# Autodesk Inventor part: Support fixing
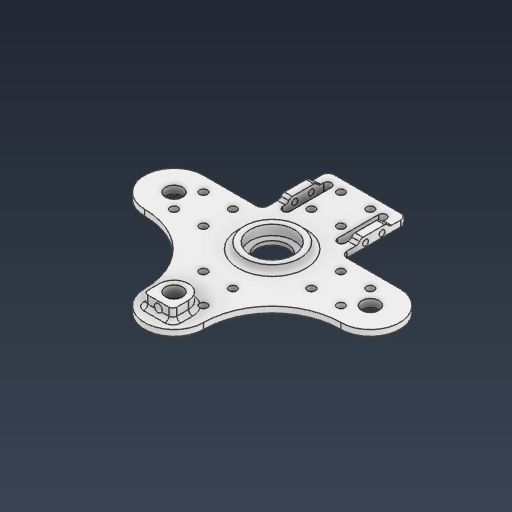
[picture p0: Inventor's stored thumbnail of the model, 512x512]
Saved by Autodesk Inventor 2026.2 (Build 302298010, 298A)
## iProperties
Created: 2026-04
Part Number: Support fixing
Material: ABS 플라스틱
Document SubType Name: Modeling
Designer: work
Density: 1.06 g/cm^3
Appearance: 매끄러움 - 흰색
Mass: 27.6357 g
Surface Area: 166.702 cm^2
Volume: 26.0714 cm^3
Author: work
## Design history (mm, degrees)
sketch "스케치1"
  geometry: L1 (0, 0)-(50, 0); L2 (0, 0)-(0, 50); L3 (0, 0)-(-50, 0); L4 (0, 0)-(0, -50); L5 (-15, 50)-(15, 50); L6 (-50, -15)-(-50, 15); L7 (15, -50)-(-15, -50); L8 (50, 15)-(50, -15); L9 (50, -15)-(-50, -15); L10 (20, -15)-(-20, -15); L11 (-20, -15)-(-20, -48.5); L12 (-20, -48.5)-(20, -48.5); L13 (20, -48.5)-(20, -15); L14 (-7.5, 42.5)-(7.5, 42.5); L15 (7.5, 42.5)-(7.5, 27.5); L16 (7.5, 27.5)-(-7.5, 27.5); L17 (-7.5, 27.5)-(-7.5, 42.5); L18 (-7.5, 42.5)-(7.5, 27.5); L19 (7.5, 42.5)-(-7.5, 27.5); L20 (-27.5, 7.5)-(-27.5, -7.5); L21 (-27.5, -7.5)-(-42.5, -7.5); L22 (-42.5, -7.5)-(-42.5, 7.5); L23 (-42.5, -7.5)-(-27.5, 7.5); L24 (-42.5, 7.5)-(-27.5, -7.5); L25 (-42.5, 7.5)-(-27.5, 7.5); L26 (-7.5, -27.5)-(7.5, -27.5); L27 (7.5, -27.5)-(7.5, -42.5); L28 (7.5, -42.5)-(-7.5, -42.5); L29 (7.5, -42.5)-(-7.5, -27.5); L30 (-7.5, -42.5)-(7.5, -27.5); L31 (-7.5, -42.5)-(-7.5, -27.5); L32 (27.5, -7.5)-(27.5, 7.5); L33 (27.5, 7.5)-(42.5, 7.5); L34 (42.5, 7.5)-(42.5, -7.5); L35 (42.5, 7.5)-(27.5, -7.5); L36 (42.5, -7.5)-(27.5, 7.5); L37 (42.5, -7.5)-(27.5, -7.5); C1 r 8 at (0, 0); C2 r 11.2 at (0, 0); C3 r 4.4 at (50, 0); C4 r 4.4 at (0, 50); C5 r 4.4 at (-50, 0); C6 r 4.4 at (0, -50); C7 r 2 at (7.5, 42.5); C8 r 2 at (-7.5, 42.5); C9 r 2 at (-7.5, 27.5); C10 r 2 at (7.5, 27.5); C11 r 2 at (-27.5, -7.5); C12 r 2 at (-42.5, -7.5); C13 r 2 at (-27.5, 7.5); C14 r 2 at (-42.5, 7.5); C15 r 2 at (7.5, -27.5); C16 r 2 at (7.5, -42.5); C17 r 2 at (-7.5, -27.5); C18 r 2 at (-7.5, -42.5); C19 r 2 at (27.5, 7.5); C20 r 2 at (42.5, 7.5); C21 r 2 at (27.5, -7.5); C22 r 2 at (42.5, -7.5); A1 r 15 centre (0, 50) between (15, 50) and (-15, 50); A2 r 15 centre (-50, 0) between (-50, 15) and (-50, -15); A3 r 15 centre (0, -50) between (-15, -50) and (15, -50); A4 r 15 centre (50, 0) between (50, -15) and (50, 15); A5 r 35 centre (50, 50) between (15, 50) and (50, 15); A6 r 35 centre (-50, 50) between (-50, 15) and (-15, 50); 10 further points
  constraints: 74 end point, 28 centre point, 25 coincident, 12 point on circle, 5 horizontal, 5 midpoint, 4 parallel, 3 tangent, 2 perpendicular, 2 point on line, 1 concentric, 117 other
  dimensions: "d0" = 16 diameter of C1; "d1" = 22.4 diameter of C2; "d2" = 50 distance of L1.start L1.end; "d3" = 8.8 diameter of C3; "d6" = 360 deg dimension on L1.start L1.end (derived); "d8" = 30 distance of L5.start L5.end; "d11" = 360 deg dimension on L1.start A1.centre (derived); "d14" = 40 distance of L11.end L12.end; "d21" = 15 distance of L15.end L16.end; "d22" = 15 distance of L14.end L15.end; "d23" = 35 distance of C1.centre point (0, 35); "d24" = 4 diameter of C7; "d25" = 4 diameter of C8; "d26" = 4 diameter of C9; "d27" = 4 diameter of C10; "d30" = 360 deg dimension on L1.start L16.end (derived); "d32" = 6 distance between parallel lines of L12 L28
  node "스케치 - 원형 패턴1" dims "d6" = 360 deg (derived)
  node "스케치 - 원형 패턴2" dims "d11" = 360 deg (derived)
  node "스케치 - 원형 패턴4" dims "d30" = 360 deg (derived)
extrude "돌출1" new body sketch "스케치1" distance "d33" = 4; taper "d34" = 0 deg
extrude "돌출2" join sketch "스케치1" distance "d35" = 2; taper "d36" = 0 deg
sketch "스케치2"
  geometry: C1 r 14.2 at (0, 0); C2 r 11.2 at (0, 0) reference; 1 further point
  constraints: 1 centre point, 1 coincident, 1 concentric
  dimensions: "d37" = 3 radial gap between concentric circles of C1 C2
extrude "돌출3" join sketch "스케치2" distance "d38" = 3; taper "d39" = 0 deg
fillet "모깎기1" dims "d40" = 3
sketch "스케치3"
  geometry: L1 (20, 38.75)-(16, 38.75); L2 (16, 38.75)-(16, 24.75); L3 (16, 24.75)-(20, 24.75); L4 (20, 24.75)-(20, 38.75); L5 (20, 18)-(20, 45.5) reference; L6 (17, 48.5)-(-17, 48.5) reference; L7 (0, 48.5)-(0, 0); L8 (-20, 38.75)-(-16, 38.75); L9 (-16, 38.75)-(-16, 24.75); L10 (-16, 24.75)-(-20, 24.75); L11 (-20, 24.75)-(-20, 38.75); 1 further point
  constraints: 18 end point, 4 symmetric about line, 3 midpoint, 2 parallel, 1 horizontal, 1 perpendicular, 1 vertical
  dimensions: "d41" = 4 distance of L2.end L3.end; "d42" = 14 distance of L1.end L2.end
extrude "돌출4" join sketch "스케치3" distance "d43" = 2; taper "d44" = 0 deg
sketch "스케치4"
  geometry: L1 (20.75, 6)-(6.75, 6) reference; L2 (13.75, 6)-(13.75, 0); L3 (9.55, 3)-(17.95, 3); L4 (20.75, 4)-(6.75, 4) reference; L5 (9.55, 3)-(17.95, 3); L6 (0, 0)-(27.5, 0) reference; C1 r 1.5 at (9.55, 3); C2 r 1.5 at (17.95, 3); 2 further points
  constraints: 6 end point, 3 midpoint, 2 centre point, 2 coincident, 1 collinear, 1 horizontal, 1 parallel, 1 vertical
  dimensions: "d45" = 8.4 distance of L3.start L3.end; "d46" = 0 distance between parallel lines of L3 L5 (derived); "d47" = 3 diameter of C1; "d48" = 3 diameter of C2; "d49" = 3 distance between parallel lines of L6 L3
extrude "돌출5" cut sketch "스케치4" distance "d50" = 4; taper "d51" = 0 deg
sketch "스케치5"
  geometry: L1 (16, 19.25)-(12, 19.25); L2 (12, 19.25)-(12, 44.25); L3 (12, 44.25)-(16, 44.25); L4 (16, 44.25)-(16, 19.25); L5 (16, 38.75)-(16, 24.75) reference; 2 further points
  constraints: 8 end point, 2 midpoint, 2 parallel, 1 horizontal, 1 perpendicular
  dimensions: "d52" = 4 distance of L2.end L3.end; "d53" = 25 distance of L1.end L2.end
extrude "돌출6" cut sketch "스케치5" distance "d54" = 4; taper "d55" = 0 deg
fillet "모깎기2" dims "d56" = 2
node "작업 평면1"
fillet "모깎기3" dims "d57" = 2
chamfer "모따기1" distance "d58" = 1; stored, may be unused: second distance "d59" = 2, angle "d60" = 45 deg
sketch "스케치6"
  geometry: L1 (-16, 40.75)-(-20, 40.75) reference; L2 (-16, 40.75)-(-16, 42.25) reference; L3 (-12, 42.25)-(-12, 21.25) reference; L4 (-16, 21.25)-(-16, 22.75) reference; L5 (-20, 22.75)-(-16, 22.75) reference; L6 (-20, 22.75)-(-20, 18) reference; L7 (-23, 15)-(-50, 15) reference; L8 (50, 15)-(23, 15) reference; L9 (20, 18)-(20, 22.75) reference; L10 (16, 22.75)-(20, 22.75) reference; L11 (16, 22.75)-(16, 21.25) reference; L12 (12, 21.25)-(12, 42.25) reference; L13 (16, 42.25)-(16, 40.75) reference; L14 (20, 40.75)-(16, 40.75) reference; L15 (20, 40.75)-(20, 45.5) reference; L16 (17, 48.5)-(-17, 48.5) reference; L17 (-20, 45.5)-(-20, 40.75) reference; L18 (7.4, -50)-(-7.4, -50); L19 (-7.4, -50)-(-7.4, -58); L20 (-7.4, -58)-(7.4, -58); L21 (7.4, -58)-(7.4, -50); C1 r 4.4 at (-50, 0) reference; C2 r 4.4 at (0, -50) reference; C3 r 4.4 at (50, 0) reference; C4 r 2 at (-27.5, 7.5) reference; C5 r 2 at (-27.5, -7.5) reference; C6 r 2 at (27.5, -7.5) reference; C7 r 2 at (27.5, 7.5) reference; C8 r 2 at (7.5, -27.5) reference; C9 r 2 at (-7.5, -42.5) reference; C10 r 2 at (7.5, -42.5) reference; C11 r 2 at (-7.5, -27.5) reference; C12 r 2 at (42.5, 7.5) reference; C13 r 2 at (42.5, -7.5) reference; C14 r 2 at (-42.5, -7.5) reference; C15 r 2 at (-42.5, 7.5) reference; C16 r 2 at (7.5, 42.5) reference; C17 r 2 at (-7.5, 42.5) reference; C18 r 2 at (-7.5, 27.5) reference; C19 r 2 at (7.5, 27.5) reference; C20 r 17.2 at (0, 0) reference; A1 r 2 centre (-14, 42.25) between (-12, 42.25) and (-16, 42.25) reference; A2 r 2 centre (-14, 21.25) between (-16, 21.25) and (-12, 21.25) reference; A3 r 3 centre (-23, 18) between (-23, 15) and (-20, 18) reference; A4 r 15 centre (-50, 0) between (-50, 15) and (-50, -15) reference; A5 r 35 centre (-50, -50) between (-15, -50) and (-50, -15) reference; A6 r 15 centre (0, -50) between (-15, -50) and (15, -50) reference; A7 r 35 centre (50, -50) between (50, -15) and (15, -50) reference; A8 r 15 centre (50, 0) between (50, -15) and (50, 15) reference; A9 r 3 centre (23, 18) between (20, 18) and (23, 15) reference; A10 r 2 centre (14, 21.25) between (12, 21.25) and (16, 21.25) reference; A11 r 2 centre (14, 42.25) between (16, 42.25) and (12, 42.25) reference; A12 r 3 centre (17, 45.5) between (20, 45.5) and (17, 48.5) reference; A13 r 3 centre (-17, 45.5) between (-17, 48.5) and (-20, 45.5) reference; A14 r 7.4 centre (0, -50) between (7.4, -50) and (-7.4, -50); 1 further point
  constraints: 8 end point, 2 parallel, 2 point on circle, 1 centre point, 1 coincident, 1 horizontal, 1 perpendicular
  dimensions: "d61" = 3 radial gap between concentric circles of A14 C2; "d62" = 8 distance of L18.end L19.end; "d63" = 14.8 distance of L19.end L20.end
extrude "돌출7" join sketch "스케치6" distance "d64" = 6; taper "d65" = 0 deg
sketch "스케치7"
  geometry: L1 (-3.8, 3)-(18.6, 3) reference; L2 (14.8, 6)-(0, 6) reference; L3 (7.4, 6)-(7.4, -4); C1 r 2 at (7.4, 3)
  constraints: 2 end point, 2 midpoint, 1 centre point, 1 vertical
  dimensions: "d66" = 4 diameter of C1
extrude "돌출8" cut sketch "스케치7" stored distance "d67" = 6; taper "d68" = 0 deg
fillet "모깎기4" dims "d69" = 2
fillet "모깎기5" dims "d70" = 2
node "솔리드1"
mirror "미러1"
node "투영된 루프1"
